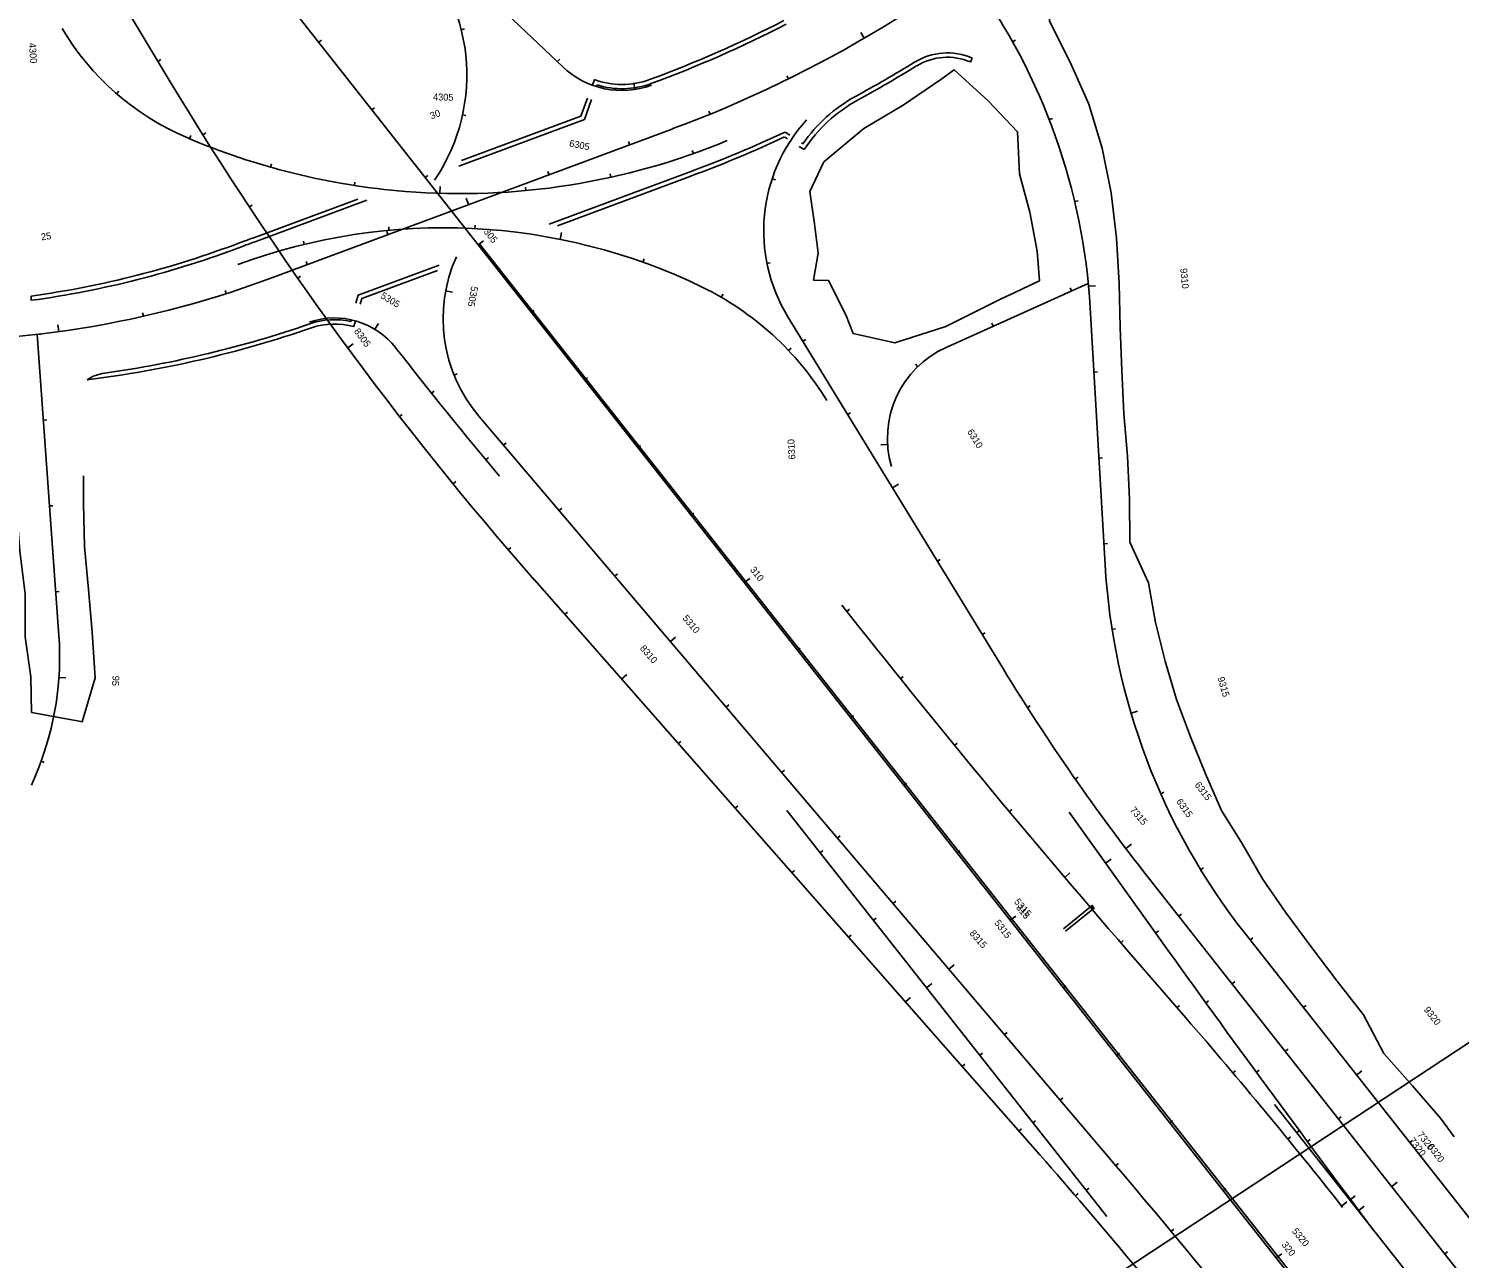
# Model space of a CAD drawing. Extents: x -5665 to 1997148, y 4 to 827579.
# Drawn here: x 1963763 to 1965427, y 803327 to 804758 of the extents above; entities that cross this region are included whole.
import ezdxf

# ---------------------------------------------------------------- set-up
doc = ezdxf.new("R2010")
doc.units = 0
for name, color, linetype in [('RD_EX_BldgApp', 7, 'Continuous'), ('RD_EX_Pavement_Markings', 7, 'Continuous'), ('RD_HC_CL_Rel', 7, 'Continuous'), ('RD_HC_Data_Tic_Rel', 7, 'Continuous'), ('RD_HC_TX_Rel_Sta50', 7, 'Continuous'), ('RD_PD_CstnLmt', 7, 'Continuous'), ('RD_PD_SW', 7, 'Continuous'), ('RD_SHT_ShtClip', 7, 'Continuous')]:
    doc.layers.add(name, color=color, linetype=linetype)

msp = doc.modelspace()

# ---------------------------------------------------------------- linework, layer by layer
at = {"layer": 'RD_EX_BldgApp'}
for p, q in [((1964966.2, 803710.7), (1965000, 803738.1)), ((1965002.4, 803735.3), (1964968.6, 803707.9))]:
    msp.add_line(p, q, dxfattribs=at)
for points in [[(1964999.7, 803735.1), (1965000.2, 803735), (1965000.8, 803735.1), (1965001.1, 803735.6), (1965001.2, 803736.1), (1965001, 803736.6), (1965000.5, 803737), (1965000, 803737), (1964999.5, 803736.7), (1964999.2, 803736.2), (1964999.3, 803735.7), (1964999.6, 803735.2), (1964999.7, 803735.1)], [(1964999.8, 803735.3), (1965000.3, 803735.2), (1965000.7, 803735.4), (1965001, 803735.8), (1965001, 803736.3), (1965000.6, 803736.7), (1965000.2, 803736.8), (1964999.7, 803736.6), (1964999.4, 803736.2), (1964999.5, 803735.7), (1964999.8, 803735.3)], [(1964999.9, 803735.5), (1965000.3, 803735.4), (1965000.7, 803735.6), (1965000.8, 803736), (1965000.6, 803736.4), (1965000.3, 803736.6), (1964999.8, 803736.5), (1964999.6, 803736.1), (1964999.7, 803735.7), (1964999.9, 803735.5)], [(1965000, 803735.7), (1965000.3, 803735.6), (1965000.6, 803735.9), (1965000.6, 803736.2), (1965000.3, 803736.4), (1964999.9, 803736.3), (1964999.8, 803736), (1965000, 803735.7), (1965000, 803735.7)], [(1965000.1, 803735.8), (1965000.3, 803735.8), (1965000.4, 803736.1), (1965000.2, 803736.2), (1965000, 803736), (1965000.1, 803735.8)]]:
    msp.add_lwpolyline(points, dxfattribs=at)
at = {"layer": 'RD_EX_Pavement_Markings'}
msp.add_line((1964286.7, 804508.1), (1966609.3, 801563.1), dxfattribs=at)
at = {"layer": 'RD_HC_CL_Rel'}
for p, q in [((1963923.8, 805151.2), (1964383.9, 804713.4)), ((1963836.3, 805076.9), (1966419.9, 801796.5)), ((1963703.7, 805069), (1963926.3, 804698.1)), ((1964041.2, 804466.4), (1964512.2, 804641.5)), ((1964830, 804387), (1964995.2, 804461.5)), ((1964997.5, 804432.9), (1965014.8, 804134.3)), ((1964645.9, 804422.5), (1964896.5, 804012.7)), ((1963772.8, 804402.1), (1963798, 804052)), ((1964286.4, 804307.1), (1965019.1, 803444.8)), ((1964351.2, 804116.5), (1964939, 803447.7)), ((1963773.7, 803896.5), (1963766.2, 803878)), ((1964644.8, 803848.3), (1965016.8, 803376)), ((1964973.1, 803846.3), (1965080.1, 803696.7)), ((1965065.4, 803770.1), (1965630.3, 803052.8)), ((1965177.5, 803705.2), (1965653.9, 803100.4)), ((1965040.1, 803686.2), (1965108.8, 803607)), ((1965211.9, 803506.4), (1965687, 802903.3))]:
    msp.add_line(p, q, dxfattribs=at)
for centre, radius, start, end in [((1964013.2, 805984.2), 1432.4, 290.3874, 312.0581), ((1964054.4, 804703.9), 218, 325.8435, 46.4277), ((1964278.7, 804391.2), 720, 3.3169, 35.9381), ((1964068.2, 804916.4), 310, 210.7484, 246.7893), ((1964452.9, 804785.9), 100, 226.4277, 290.1469), ((1967355.7, 806757.1), 4000, 210.9813, 221.3125), ((1964809.7, 804522.7), 192, 137.7696, 211.4468), ((1964265.3, 805375.9), 810, 246.7893, 265.4446), ((1964265.3, 805375.9), 810, 265.4446, 292.5082), ((1964245.5, 803836.2), 690, 64.1687, 110.2967), ((1963642, 805540.6), 1145.9, 242.401, 290.3874), ((1964419.8, 804420.4), 175, 155.7307, 220.3531), ((1964392.7, 804142.6), 350, 31.4468, 64.0081), ((1964118.7, 804331.3), 90, 37.9621, 109.0548), ((1968486.5, 807739.2), 5450, 217.9621, 219.9837), ((1964877.6, 804281.3), 116, 114.2548, 196.3567), ((1965778.5, 804178.6), 765, 183.3169, 218.2244), ((1973359.6, 810900.9), 11012, 218.22442, 220.93208), ((1963448.9, 804026.9), 350, 338.1302, 4.1175), ((1967029.3, 805316.9), 2500, 211.4468, 218.2244), ((1978920.3, 813595.8), 17016, 215.57401, 216.98206), ((1960538.1, 799643.3), 6050, 38.22442, 40.93208), ((1960423.3, 799478.7), 6012, 38.22442, 41.31254), ((1956636.4, 796322.3), 11000, 38.22442, 40.35314)]:
    msp.add_arc(centre, radius, start, end, dxfattribs=at)
at = {"layer": 'RD_HC_Data_Tic_Rel'}
for p, q in [((1964100.1, 804741.8), (1964103.3, 804744.3)), ((1964266, 804756.6), (1964269.9, 804757.6)), ((1964734.5, 804746.6), (1964730.5, 804753.5)), ((1964907.2, 804742.5), (1964910.7, 804744.4)), ((1963913.3, 804719.9), (1963916.7, 804721.9)), ((1964377.6, 804719.4), (1964380.4, 804722.3)), ((1964468, 804687), (1964466.8, 804694.9)), ((1964646.4, 804699.3), (1964644.7, 804702.9)), ((1963865.1, 804682.2), (1963867.7, 804685.3)), ((1964162, 804663.3), (1964165.2, 804665.8)), ((1964555.3, 804658.3), (1964553.8, 804662)), ((1964267.4, 804657.5), (1964271.4, 804656.7)), ((1964949.8, 804652.1), (1964953.5, 804653.5)), ((1963949.8, 804629.9), (1963951.3, 804633.6)), ((1963965.3, 804634.5), (1963968.7, 804636.6)), ((1964461.8, 804622.7), (1964460.4, 804626.5)), ((1964535.9, 804612.5), (1964534.6, 804616.2)), ((1964044, 804596.7), (1964045.1, 804600.6)), ((1964141.7, 804575.4), (1964142.3, 804579.4)), ((1964223.9, 804584.7), (1964227, 804587.2)), ((1964368.1, 804587.9), (1964366.7, 804591.7)), ((1964439.8, 804584.9), (1964439, 804588.8)), ((1964627.5, 804583.2), (1964631.3, 804581.9)), ((1964241.2, 804566.3), (1964241.4, 804574.3)), ((1964274.3, 804553.1), (1964271.5, 804560.6)), ((1964341.1, 804569.5), (1964340.7, 804573.5)), ((1964019.5, 804550.4), (1964022.8, 804552.6)), ((1964979.4, 804556.7), (1964983.3, 804557.6)), ((1964181.9, 804523.2), (1964181.6, 804527.2)), ((1964281.8, 804525.2), (1964282, 804529.2)), ((1964083.4, 804506.9), (1964082.4, 804510.8)), ((1964180.6, 804518.2), (1964179.2, 804522)), ((1964285.8, 804506.2), (1964292, 804511.1)), ((1964380.9, 804512.7), (1964382.5, 804520.6)), ((1964086.9, 804483.4), (1964085.5, 804487.1)), ((1964477.2, 804486.1), (1964478.6, 804489.9)), ((1964621.5, 804484.5), (1964625.4, 804485.3)), ((1964075.7, 804467.7), (1964078.9, 804470)), ((1963992.7, 804449.6), (1963991.5, 804453.4)), ((1964247.8, 804452.9), (1964255.7, 804451.4)), ((1964568.4, 804445.3), (1964570.4, 804448.8)), ((1964975.7, 804452.7), (1964974.1, 804456.3)), ((1964995.6, 804458.1), (1965003.5, 804458.8)), ((1963896.3, 804423.2), (1963895.4, 804427.1)), ((1964347.6, 804427.6), (1964350.8, 804430.1)), ((1963798, 804405.3), (1963796.9, 804413.2)), ((1964165.5, 804408.2), (1964169.6, 804415)), ((1964884.5, 804411.6), (1964882.9, 804415.2)), ((1963772.8, 804402.1), (1963776.8, 804402.4)), ((1964663.1, 804394.3), (1964666.6, 804396.4)), ((1964133.9, 804386.4), (1964140.4, 804391.2)), ((1964646.6, 804383.5), (1964649.5, 804386.3)), ((1964796.9, 804364.6), (1964794.1, 804367.4)), ((1964257.6, 804354.7), (1964261.3, 804356.2)), ((1964409.5, 804349), (1964412.6, 804351.5)), ((1965001.8, 804358.3), (1965005.8, 804358.5)), ((1964231.5, 804333.7), (1964234.6, 804336.2)), ((1964715.3, 804309), (1964718.7, 804311.1)), ((1963780, 804302.4), (1963783.9, 804302.7)), ((1964194.2, 804306.7), (1964197.3, 804309.1)), ((1964315, 804273.5), (1964318, 804276.1)), ((1964471.4, 804270.5), (1964474.5, 804273)), ((1964761.8, 804274.2), (1964753.9, 804273.7)), ((1964294.7, 804256.3), (1964297.7, 804258.8)), ((1965007.6, 804258.4), (1965011.6, 804258.7)), ((1964256.4, 804228.4), (1964259.5, 804230.9)), ((1964767.5, 804223.7), (1964774.3, 804227.8)), ((1963787.1, 804202.6), (1963791.1, 804202.9)), ((1964379.7, 804197.3), (1964382.8, 804199.9)), ((1964533.3, 804191.9), (1964536.4, 804194.4)), ((1964320.6, 804151.7), (1964323.6, 804154.3)), ((1965013.4, 804158.6), (1965017.4, 804158.8)), ((1964819.7, 804138.4), (1964823.1, 804140.4)), ((1964444.5, 804121.1), (1964447.5, 804123.7)), ((1964595.1, 804113.4), (1964601.4, 804118.3)), ((1963794.3, 804102.9), (1963798.3, 804103.2)), ((1964386.4, 804076.4), (1964389.4, 804079.1)), ((1964714.4, 804080), (1964717.5, 804082.4)), ((1965022.9, 804059.1), (1965026.8, 804059.7)), ((1964509.2, 804044.9), (1964515.3, 804050.1)), ((1964871.8, 804053), (1964875.2, 804055.1)), ((1964657, 804034.8), (1964660.1, 804037.3)), ((1963798.1, 804003.1), (1963806.1, 804002.5)), ((1964452.4, 804001.3), (1964458.4, 804006.6)), ((1964776.7, 804001.7), (1964779.8, 804004.3)), ((1964574, 803968.7), (1964577, 803971.3)), ((1964924.5, 803968), (1964927.8, 803970.2)), ((1965044.9, 803961.6), (1965052.6, 803963.9)), ((1964718.9, 803956.2), (1964722, 803958.7)), ((1964518.4, 803926.2), (1964521.5, 803928.8)), ((1964839.7, 803924.1), (1964842.8, 803926.6)), ((1963777.2, 803905.6), (1963781, 803904.2)), ((1964638.7, 803892.5), (1964641.8, 803895.1)), ((1964780.8, 803877.7), (1964783.9, 803880.2)), ((1964980.1, 803884.9), (1964983.4, 803887.2)), ((1965079.4, 803867.9), (1965083.1, 803869.5)), ((1964584.5, 803851.1), (1964587.5, 803853.7)), ((1964903.4, 803847), (1964906.4, 803849.6)), ((1964703.5, 803816.3), (1964706.5, 803818.9)), ((1964683.4, 803799.3), (1964686.5, 803801.7)), ((1964842.6, 803799.1), (1964845.8, 803801.6)), ((1965039, 803804.1), (1965045.4, 803809)), ((1964650.5, 803776), (1964653.5, 803778.6)), ((1965015.4, 803787.2), (1965021.9, 803791.9)), ((1965125.9, 803779.4), (1965129.3, 803781.5)), ((1964967.8, 803770.5), (1964973.9, 803775.7)), ((1964768.2, 803740.1), (1964771.3, 803742.7)), ((1965100.6, 803725.3), (1965103.7, 803727.8)), ((1964745.3, 803720.7), (1964748.4, 803723.2)), ((1964904.5, 803720.6), (1964910.8, 803725.5)), ((1964716.5, 803700.9), (1964719.5, 803703.5)), ((1965032.9, 803694.6), (1965035.9, 803697.2)), ((1965073.6, 803705.9), (1965076.8, 803708.2)), ((1965183.5, 803697.7), (1965186.6, 803700.2)), ((1964833, 803663.9), (1964839.1, 803669)), ((1964807.1, 803642.1), (1964813.4, 803647.1)), ((1964966.4, 803642), (1964969.5, 803644.5)), ((1965162.5, 803646.8), (1965165.6, 803649.3)), ((1964782.5, 803625.7), (1964788.5, 803631)), ((1965131.9, 803624.7), (1965135.2, 803627)), ((1965098.4, 803619), (1965101.4, 803621.7)), ((1965245.3, 803619.1), (1965248.5, 803621.6)), ((1964897.7, 803587.7), (1964900.8, 803590.2)), ((1964869, 803563.6), (1964872.2, 803566.1)), ((1965028.2, 803563.4), (1965031.4, 803565.9)), ((1965224.3, 803568.2), (1965227.5, 803570.7)), ((1964848.5, 803550.6), (1964851.5, 803553.3)), ((1965163.4, 803543.1), (1965166.5, 803545.7)), ((1965190.8, 803543.8), (1965194, 803546.2)), ((1965307.2, 803540.6), (1965313.5, 803545.5)), ((1964962.5, 803511.4), (1964965.5, 803514)), ((1964914.5, 803475.5), (1964917.5, 803478.2)), ((1964930.9, 803485), (1964934, 803487.5)), ((1965090.1, 803484.9), (1965093.3, 803487.4)), ((1965286.2, 803489.7), (1965289.4, 803492.1)), ((1965227.3, 803466.1), (1965230.4, 803468.7)), ((1965237.6, 803473.8), (1965240.8, 803476.2)), ((1965250.1, 803463.3), (1965253.3, 803465.7)), ((1965369.1, 803462), (1965372.2, 803464.5)), ((1965027.2, 803435.2), (1965030.3, 803437.8)), ((1965348.1, 803411.1), (1965354.4, 803416.1)), ((1964980.3, 803400.2), (1964983.3, 803402.8)), ((1964992.8, 803406.5), (1964995.9, 803408.9)), ((1965152, 803406.3), (1965155.1, 803408.8)), ((1965299.5, 803395.2), (1965305.8, 803400.2)), ((1965289.8, 803388.1), (1965296.1, 803393.1)), ((1965309.8, 803383.1), (1965316.2, 803387.9)), ((1965091.5, 803358.7), (1965094.6, 803361.2)), ((1965213.9, 803327.8), (1965220.2, 803332.7)), ((1965410, 803332.5), (1965413.1, 803335))]:
    msp.add_line(p, q, dxfattribs=at)
at = {"layer": 'RD_PD_CstnLmt'}
for points in [[(1965224.5, 803730), (1965197.9, 803769), (1965174.7, 803809.3), (1965150, 803848.5), (1965131.6, 803891), (1965114.1, 803933.9), (1965097.9, 803977.3), (1965084.8, 804021.9), (1965073.5, 804067.1), (1965065.3, 804113.2), (1965043.4, 804160.3), (1965043.1, 804210.4), (1965040.7, 804260.4), (1965036.6, 804310.2), (1965034.2, 804360.1), (1965032.4, 804410.1), (1965031.1, 804461.4), (1965028, 804514), (1965021.9, 804566.7), (1965011.4, 804618.9), (1964995.7, 804670), (1964974.1, 804718.8), (1964950.2, 804766.5), (1964948.5, 804817)], [(1964823.8, 804698.7), (1964839.3, 804710), (1964878.9, 804673.9), (1964912.7, 804637.7), (1964915.3, 804589.1), (1964927.1, 804544.3), (1964935.8, 804498.9), (1964938.5, 804464.6)], [(1964823.8, 804698.7), (1964779.9, 804668.8), (1964734.1, 804641.8)], [(1964734.1, 804641.8), (1964687.6, 804602.8), (1964687.4, 804602.3), (1964671.4, 804568.6), (1964676.6, 804530.7), (1964681.1, 804496.6), (1964675.8, 804465.4), (1964675.8, 804465.4), (1964693, 804464.8), (1964713.2, 804424.9), (1964721.7, 804403.1)], [(1964721.7, 804403.1), (1964770.2, 804392.2), (1964829.7, 804411.5), (1964874.4, 804434), (1964894.5, 804443.8), (1964908.2, 804450), (1964919.6, 804455.4), (1964938.5, 804464.6)], [(1963736.9, 804325.2), (1963740.5, 804299.5), (1963742.5, 804249.6), (1963748.8, 804199.9), (1963752.4, 804150), (1963758.6, 804100.3), (1963758.6, 804050.2), (1963765.3, 804003.7), (1963766.2, 803962.4), (1963766.9, 803962.3), (1963768.3, 803962), (1963795.9, 803957), (1963823.4, 803951.9), (1963824.9, 803951.6), (1963824.9, 803951.6), (1963840.2, 804002.5), (1963836.6, 804055.8), (1963832.4, 804105.6), (1963827.7, 804155.4), (1963826.7, 804205.5), (1963826.4, 804237.5)], [(1965420.7, 803468.9), (1965404.9, 803490.3), (1965372.2, 803528.1), (1965339, 803565.6), (1965315.4, 803610.7), (1965284.5, 803650), (1965254.4, 803689.9), (1965224.5, 803730)]]:
    msp.add_lwpolyline(points, dxfattribs=at)
at = {"layer": 'RD_PD_SW'}
for p, q in [((1964860.2, 804723.6), (1964858.2, 804719)), ((1964420.8, 804698.6), (1964418.4, 804692)), ((1964423.8, 804692.3), (1964423.1, 804690.4)), ((1964405.2, 804656.1), (1964412.9, 804677)), ((1964409.1, 804652.2), (1964417.6, 804675.4)), ((1964263.1, 804598), (1964409.1, 804652.2)), ((1964266.3, 804604.5), (1964405.2, 804656.1)), ((1964642.1, 804631.8), (1964645.4, 804629.6)), ((1964642.5, 804637.5), (1964648.2, 804633.8)), ((1964664.7, 804617.1), (1964658.8, 804620.9)), ((1964663.3, 804624), (1964661.6, 804625.1)), ((1964368.3, 804530.4), (1964531.1, 804590.9)), ((1964377.9, 804528.6), (1964532.8, 804586.2)), ((1964023.4, 804514.2), (1964145.6, 804559.6)), ((1964025.1, 804509.5), (1964156, 804558.2)), ((1964146.1, 804447.8), (1964240.3, 804482.8)), ((1964150.2, 804444), (1964238.3, 804476.7)), ((1963765.6, 804446.8), (1963765.9, 804441.8)), ((1964146.1, 804447.8), (1964143.5, 804438.5)), ((1964150.2, 804444), (1964148.3, 804437.3)), ((1964137.5, 804417.3), (1964138.1, 804419.2)), ((1964141, 804411.2), (1964142.9, 804418))]:
    msp.add_line(p, q, dxfattribs=at)
for centre, radius, start, end in [((1964013.2, 805984.2), 1369.4, 290.1469, 297.2985), ((1964013.2, 805984.2), 1374.4, 290.1469, 297.3115), ((1964831.3, 804656.6), 73, 66.7023, 121.6403), ((1964013.2, 805984.2), 1486.4, 298.5815, 301.6403), ((1964013.2, 805984.2), 1491.4, 298.5815, 301.6403), ((1964831.3, 804656.6), 68, 66.7023, 121.6403), ((1964452.9, 804785.9), 93, 249.8307, 290.1469), ((1964452.9, 804785.9), 98, 252.7523, 290.1469), ((1964809.7, 804522.7), 178, 118.5884, 145.3211), ((1964809.7, 804522.7), 173, 118.5884, 146.9307), ((1964013.2, 805984.2), 1486.4, 290.3874, 295.0451), ((1964013.2, 805984.2), 1491.4, 290.3874, 294.9383), ((1963616.7, 805536.3), 1099.6, 277.7805, 290.8813), ((1963642, 805540.6), 1094.9, 289.5662, 290.3874), ((1963642, 805540.6), 1099.9, 289.5662, 290.3874), ((1963616.7, 805536.3), 1104.6, 277.7639, 290.873), ((1963676, 805613), 1273, 276.9904, 289.0548), ((1963676, 805613), 1268, 277.9346, 289.0548), ((1964118.7, 804331.3), 88, 77.6265, 109.0548), ((1964118.7, 804331.3), 83, 74.3693, 109.0548), ((1963857.6, 804309.6), 48, 97.9346, 123.8508)]:
    msp.add_arc(centre, radius, start, end, dxfattribs=at)
at = {"layer": 'RD_SHT_ShtClip'}
msp.add_lwpolyline([(1962404, 800141.4), (1962156.8, 800249.1), (1961619.9, 801061.9), (1967047, 804639.1), (1967746.1, 803578.5), (1967695.1, 802969), (1968000.2, 801689.9), (1968522.9, 801587.9), (1968575.1, 801281.2), (1968568.4, 800839.6), (1968542.7, 800594.7), (1964601.3, 797996.7), (1963740.9, 798826.2)], close=True, dxfattribs=at)

# ---------------------------------------------------------------- texts
at = {"layer": 'RD_HC_TX_Rel_Sta50'}
for s, rotation, p in [('4300', 274.2965, (1963763, 804741)), ('4305', 358.2954, (1964233, 804674.6)), ('30', 20.3874, (1964231.4, 804652.3)), ('6305', 348.6757, (1964391, 804620.9)), ('25', 7.8254, (1963777.7, 804511.5)), ('305', 308.2244, (1964291.5, 804521.5)), ('9310', 275.3251, (1965102.1, 804478.7)), ('5305', 328.6727, (1964171.3, 804445.1)), ('5305', 259.3104, (1964277.7, 804458.7)), ('8305', 306.3469, (1964140.7, 804405.7)), ('6310', 93.4898, (1964654.7, 804256.9)), ('6310', 301.4468, (1964854, 804289.1)), ('310', 308.2244, (1964601.3, 804128.2)), ('5310', 310.3531, (1964522.7, 804071.7)), ('8310', 311.3125, (1964473.2, 804036.5)), ('95', 266.0961, (1963860.5, 804005.4)), ('9315', 286.4749, (1965145.4, 804002.5)), ('6315', 307.2377, (1965118.5, 803878)), ('6315', 305.574, (1965097, 803858.7)), ('7315', 310.354, (1965043.2, 803848.6)), ('5315', 310.3531, (1964908.4, 803741.9)), ('315', 308.2244, (1964910.7, 803735.3)), ('5315', 308.2244, (1964885.4, 803717.4)), ('8315', 311.3125, (1964856.6, 803705.1)), ('9320', 308.2244, (1965385, 803616.4)), ('7320', 308.2417, (1965367.6, 803463.9)), ('7320', 308.2244, (1965377.3, 803471)), ('6320', 306.8829, (1965389.4, 803457.1)), ('5320', 309.2463, (1965231.6, 803358.7)), ('320', 308.2244, (1965219.6, 803343.1))]:
    msp.add_text(s, height=8, rotation=rotation, dxfattribs=at).set_placement(p)

doc.saveas('drawing.dxf')
